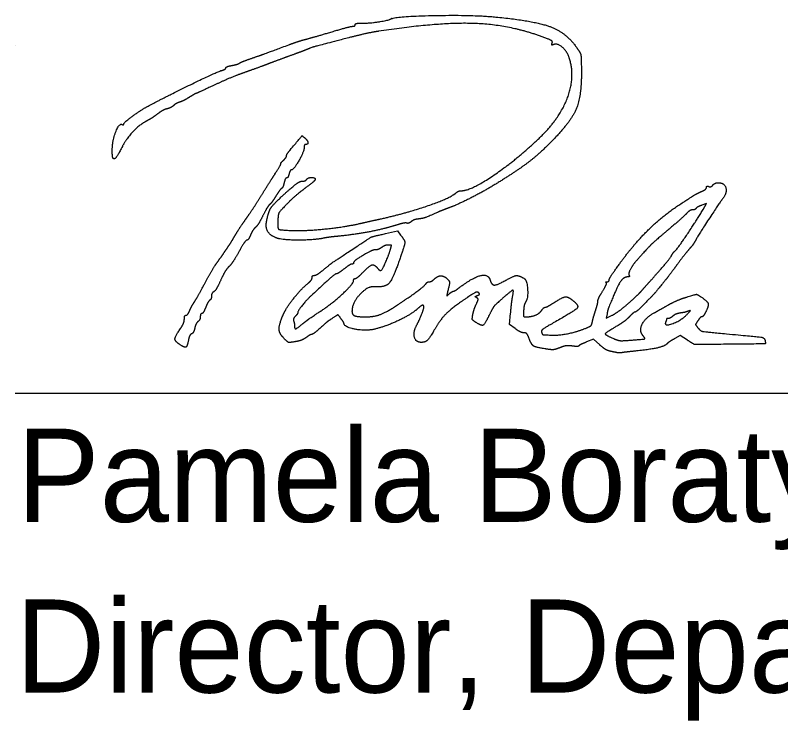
# Model space of a CAD drawing. Extents: x 0 to 34, y 0 to 22.
# Drawn here: x 25.87 to 27.021, y 4.243 to 5.303 of the extents above; entities that cross this region are included whole.
import ezdxf

# ---------------------------------------------------------------- set-up
doc = ezdxf.new("R2010")
doc.units = 0
for name, color, linetype in [('Default', 7, 'Continuous'), ('GM_X_Adjacent_County', 7, 'Continuous'), ('GM_X_Township', 7, 'Continuous')]:
    doc.layers.add(name, color=color, linetype=linetype)

msp = doc.modelspace()

# ---------------------------------------------------------------- linework, layer by layer
at = {"layer": 'Default'}
for points in [[(26.9038, 5.0114), (26.9092, 5.0203), (26.9019, 5.0178)], [(26.4265, 4.9752), (26.4445, 4.9793), (26.4492, 4.9731)], [(26.6215, 4.8324), (26.6131, 4.8388), (26.6146, 4.8558)], [(26.7595, 4.8544), (26.7584, 4.8479), (26.7671, 4.8524)], [(26.8803, 4.8151), (26.8696, 4.8219), (26.8613, 4.8174)], [(26.7484, 4.8081), (26.7393, 4.8164), (26.7287, 4.8123)]]:
    msp.add_lwpolyline(points, dxfattribs=at)
for points in [[(26.3899, 5.2916), (26.3995, 5.2913), (26.4305, 5.2957), (26.4339, 5.2978)], [(26.4339, 5.2978), (26.4407, 5.302), (26.5577, 5.3043), (26.5921, 5.3009)], [(26.5921, 5.3009), (26.6514, 5.2951), (26.6989, 5.2768), (26.7147, 5.2537)], [(26.3442, 5.2782), (26.3603, 5.283), (26.3751, 5.2869), (26.3772, 5.2869)], [(26.3772, 5.2869), (26.3792, 5.2869), (26.3809, 5.288), (26.3809, 5.2894)], [(26.3809, 5.2894), (26.3809, 5.2907), (26.385, 5.2917), (26.3899, 5.2916)], [(26.6646, 5.2702), (26.6141, 5.2892), (26.5061, 5.2931), (26.4157, 5.2794)], [(26.3053, 5.2671), (26.3106, 5.2684), (26.3281, 5.2734), (26.3442, 5.2782)], [(26.3713, 5.2697), (26.3203, 5.2565), (26.316, 5.2552), (26.3053, 5.2509)], [(26.4157, 5.2794), (26.4065, 5.278), (26.3865, 5.2736), (26.3713, 5.2697)], [(26.6769, 5.2615), (26.6779, 5.264), (26.6745, 5.2665), (26.6646, 5.2702)], [(26.2249, 5.2387), (26.2396, 5.2437), (26.2461, 5.2461), (26.2813, 5.2592)], [(26.2813, 5.2592), (26.2893, 5.2622), (26.3001, 5.2657), (26.3053, 5.2671)], [(26.6793, 5.2595), (26.6767, 5.2585), (26.676, 5.2591), (26.6769, 5.2615)], [(26.7027, 5.2395), (26.6995, 5.2493), (26.685, 5.2616), (26.6793, 5.2595)], [(26.3053, 5.2509), (26.3027, 5.2498), (26.2924, 5.246), (26.2825, 5.2424)], [(26.7147, 5.2537), (26.7197, 5.2465), (26.7206, 5.2421), (26.7209, 5.2243)], [(26.2069, 5.2315), (26.2083, 5.2325), (26.2164, 5.2357), (26.2249, 5.2387)], [(26.2825, 5.2424), (26.2726, 5.2388), (26.2575, 5.2332), (26.2489, 5.23)], [(26.6572, 5.1184), (26.6882, 5.1478), (26.712, 5.2113), (26.7027, 5.2395)], [(26.1811, 5.2208), (26.1841, 5.2217), (26.1865, 5.2233), (26.1865, 5.2244)], [(26.1865, 5.2244), (26.1865, 5.2254), (26.1906, 5.2271), (26.1955, 5.228)], [(26.1955, 5.228), (26.2005, 5.2289), (26.2056, 5.2305), (26.2069, 5.2315)], [(26.2489, 5.23), (26.2404, 5.2267), (26.2242, 5.2208), (26.2129, 5.2169)], [(26.7209, 5.2243), (26.7217, 5.1835), (26.7056, 5.1438), (26.6762, 5.1139)], [(26.0689, 5.1665), (26.0992, 5.1827), (26.1728, 5.2184), (26.1811, 5.2208)], [(26.2129, 5.2169), (26.2017, 5.2129), (26.1814, 5.2043), (26.1677, 5.1978)], [(26.1677, 5.1978), (26.1541, 5.1914), (26.1424, 5.1861), (26.1419, 5.1861)], [(26.1319, 5.1804), (26.127, 5.1773), (26.1203, 5.1739), (26.117, 5.1729)], [(26.1419, 5.1861), (26.1413, 5.1861), (26.1368, 5.1835), (26.1319, 5.1804)], [(26.0329, 5.1399), (26.0329, 5.142), (26.0583, 5.1608), (26.0689, 5.1665)], [(26.1079, 5.1678), (26.1061, 5.166), (26.1017, 5.1638), (26.0982, 5.1629)], [(26.117, 5.1729), (26.1138, 5.1719), (26.1097, 5.1696), (26.1079, 5.1678)], [(26.0833, 5.1548), (26.0787, 5.1513), (26.0716, 5.1466), (26.0674, 5.1445)], [(26.0982, 5.1629), (26.0946, 5.1621), (26.088, 5.1584), (26.0833, 5.1548)], [(26.0674, 5.1445), (26.057, 5.1392), (26.0371, 5.1183), (26.0309, 5.1062)], [(26.0158, 5.102), (26.0159, 5.1152), (26.0265, 5.1418), (26.0306, 5.1392)], [(26.0306, 5.1392), (26.0319, 5.1384), (26.0329, 5.1387), (26.0329, 5.1399)], [(26.2831, 5.1009), (26.3017, 5.1231), (26.301, 5.1225), (26.3051, 5.1191)], [(26.3065, 5.1093), (26.3052, 5.1093), (26.3041, 5.107), (26.3041, 5.1042)], [(26.3051, 5.1191), (26.3093, 5.1155), (26.3103, 5.1093), (26.3065, 5.1093)], [(26.5405, 5.0397), (26.5546, 5.0397), (26.6227, 5.0856), (26.6572, 5.1184)], [(26.6762, 5.1139), (26.6576, 5.095), (26.6252, 5.0701), (26.5947, 5.0513)], [(26.0171, 5.0883), (26.0163, 5.0891), (26.0157, 5.0952), (26.0158, 5.102)], [(26.0309, 5.1062), (26.0243, 5.0933), (26.019, 5.0864), (26.0171, 5.0883)], [(26.2777, 5.0923), (26.2777, 5.0935), (26.2802, 5.0974), (26.2831, 5.1009)], [(26.3041, 5.1042), (26.3041, 5.0986), (26.2882, 5.0709), (26.285, 5.0709)], [(26.2692, 5.0805), (26.2686, 5.0805), (26.2703, 5.0826), (26.2729, 5.0853)], [(26.2729, 5.0853), (26.2756, 5.0879), (26.2777, 5.0911), (26.2777, 5.0923)], [(26.2602, 5.0648), (26.2657, 5.0734), (26.2698, 5.0805), (26.2692, 5.0805)], [(26.2381, 5.0298), (26.2447, 5.0404), (26.2547, 5.0562), (26.2602, 5.0648)], [(26.2815, 5.0649), (26.2807, 5.0616), (26.2791, 5.0589), (26.2779, 5.0589)], [(26.285, 5.0709), (26.2839, 5.0709), (26.2824, 5.0682), (26.2815, 5.0649)], [(26.2693, 5.0299), (26.285, 5.0445), (26.2978, 5.0541), (26.3017, 5.0541)], [(26.2741, 5.0517), (26.2733, 5.0478), (26.2715, 5.0439), (26.2702, 5.0431)], [(26.2779, 5.0589), (26.2767, 5.0589), (26.275, 5.0556), (26.2741, 5.0517)], [(26.3017, 5.0541), (26.3042, 5.0541), (26.3069, 5.0552), (26.3077, 5.0565)], [(26.3209, 5.0568), (26.3209, 5.0557), (26.3142, 5.0498), (26.3059, 5.0437)], [(26.3077, 5.0565), (26.3095, 5.0594), (26.3209, 5.0597), (26.3209, 5.0568)], [(26.5947, 5.0513), (26.5755, 5.0394), (26.5342, 5.0184), (26.5201, 5.0133)], [(26.9186, 5.0482), (26.9202, 5.0501), (26.9239, 5.0517), (26.9268, 5.0517)], [(26.9268, 5.0517), (26.9363, 5.0517), (26.94, 5.0356), (26.9326, 5.0267)], [(26.2702, 5.0431), (26.269, 5.0423), (26.2652, 5.0372), (26.2618, 5.0317)], [(26.3059, 5.0437), (26.2977, 5.0376), (26.2852, 5.0268), (26.2781, 5.0196)], [(26.5323, 5.0363), (26.5344, 5.0382), (26.5381, 5.0397), (26.5405, 5.0397)], [(26.9011, 5.0383), (26.9054, 5.0402), (26.9089, 5.0431), (26.9089, 5.0446)], [(26.9089, 5.0446), (26.9089, 5.0461), (26.9105, 5.0468), (26.9124, 5.0461)], [(26.9124, 5.0461), (26.9142, 5.0453), (26.9171, 5.0463), (26.9186, 5.0482)], [(26.2164, 4.9969), (26.2217, 5.0043), (26.2315, 5.0192), (26.2381, 5.0298)], [(26.248, 4.9953), (26.2507, 5.0083), (26.2569, 5.0183), (26.2693, 5.0299)], [(26.2618, 5.0317), (26.2584, 5.0262), (26.2543, 5.0206), (26.2526, 5.0192)], [(26.4205, 4.9977), (26.4575, 5.0059), (26.5237, 5.0288), (26.5323, 5.0363)], [(26.8722, 5.0213), (26.8911, 5.0335), (26.8929, 5.0346), (26.9011, 5.0383)], [(26.2526, 5.0192), (26.2509, 5.0179), (26.2463, 5.0103), (26.2422, 5.0023)], [(26.2781, 5.0196), (26.2674, 5.0086), (26.2653, 5.005), (26.2647, 4.9967)], [(26.7775, 4.9288), (26.7998, 4.9596), (26.8448, 5.0036), (26.8722, 5.0213)], [(26.9326, 5.0267), (26.9285, 5.0216), (26.8956, 4.9712), (26.8925, 4.965)], [(26.9019, 5.0178), (26.8978, 5.0164), (26.8939, 5.0142), (26.8932, 5.013)], [(26.5045, 5.0071), (26.4874, 4.9997), (26.4825, 4.998), (26.4759, 4.9972)], [(26.5201, 5.0133), (26.5155, 5.0117), (26.5085, 5.0089), (26.5045, 5.0071)], [(26.879, 5.0055), (26.8763, 5.0025), (26.8639, 4.9914), (26.8513, 4.9809)], [(26.861, 4.9485), (26.8639, 4.9504), (26.8921, 4.9919), (26.9038, 5.0114)], [(26.8879, 5.0109), (26.8857, 5.0109), (26.8817, 5.0084), (26.879, 5.0055)], [(26.8932, 5.013), (26.8924, 5.0118), (26.8901, 5.0109), (26.8879, 5.0109)], [(26.1997, 4.9713), (26.2035, 4.9779), (26.211, 4.9894), (26.2164, 4.9969)], [(26.2422, 5.0023), (26.2382, 4.9943), (26.2332, 4.9863), (26.231, 4.9845)], [(26.2633, 4.9684), (26.2529, 4.9723), (26.2458, 4.9848), (26.248, 4.9953)], [(26.2647, 4.9967), (26.2639, 4.9833), (26.2679, 4.9804), (26.2885, 4.9799)], [(26.3869, 4.9902), (26.3949, 4.992), (26.41, 4.9954), (26.4205, 4.9977)], [(26.4759, 4.9972), (26.4721, 4.9968), (26.4672, 4.995), (26.4651, 4.9932)], [(26.231, 4.9845), (26.2288, 4.9827), (26.2256, 4.9777), (26.2237, 4.9733)], [(26.2885, 4.9799), (26.3078, 4.9793), (26.3656, 4.9854), (26.3869, 4.9902)], [(26.4403, 4.9873), (26.4239, 4.982), (26.3788, 4.9735), (26.355, 4.9712)], [(26.4583, 4.991), (26.4567, 4.9916), (26.4486, 4.9899), (26.4403, 4.9873)], [(26.4651, 4.9932), (26.463, 4.9914), (26.46, 4.9904), (26.4583, 4.991)], [(26.1866, 4.9506), (26.1899, 4.9554), (26.1958, 4.9647), (26.1997, 4.9713)], [(26.2237, 4.9733), (26.2219, 4.9689), (26.2193, 4.9653), (26.218, 4.9653)], [(26.355, 4.9712), (26.3466, 4.9704), (26.3375, 4.9692), (26.3346, 4.9686)], [(26.3725, 4.9488), (26.4042, 4.9698), (26.4056, 4.9705), (26.4265, 4.9752)], [(26.4492, 4.9731), (26.4558, 4.9643), (26.4557, 4.9595), (26.4479, 4.9369)], [(26.8513, 4.9809), (26.8317, 4.9644), (26.82, 4.953), (26.8033, 4.9341)], [(26.218, 4.9653), (26.2167, 4.9653), (26.2113, 4.9574), (26.206, 4.9477)], [(26.3346, 4.9686), (26.3209, 4.9655), (26.2714, 4.9654), (26.2633, 4.9684)], [(26.8925, 4.965), (26.8907, 4.9615), (26.8868, 4.9561), (26.8838, 4.9529)], [(26.1731, 4.9314), (26.1772, 4.9372), (26.1833, 4.9459), (26.1866, 4.9506)], [(26.206, 4.9477), (26.2006, 4.9381), (26.194, 4.9281), (26.1911, 4.9255)], [(26.3333, 4.9209), (26.347, 4.932), (26.3451, 4.9306), (26.3725, 4.9488)], [(26.4022, 4.9477), (26.3878, 4.9398), (26.3785, 4.9334), (26.3785, 4.9314)], [(26.4119, 4.9509), (26.4097, 4.9509), (26.4053, 4.9495), (26.4022, 4.9477)], [(26.4207, 4.9544), (26.4181, 4.9525), (26.4142, 4.9509), (26.4119, 4.9509)], [(26.4192, 4.9197), (26.421, 4.9197), (26.4307, 4.9408), (26.4339, 4.9515)], [(26.4306, 4.958), (26.4277, 4.958), (26.4232, 4.9563), (26.4207, 4.9544)], [(26.4339, 4.9515), (26.4356, 4.9573), (26.4351, 4.9581), (26.4306, 4.958)], [(26.8571, 4.9433), (26.8583, 4.9455), (26.8601, 4.9478), (26.861, 4.9485)], [(26.8838, 4.9529), (26.8809, 4.9496), (26.8719, 4.9383), (26.8641, 4.9276)], [(26.4479, 4.9369), (26.4377, 4.907), (26.4257, 4.894), (26.4097, 4.8953)], [(26.8258, 4.9055), (26.8412, 4.9226), (26.8547, 4.939), (26.8571, 4.9433)], [(26.1542, 4.8993), (26.1605, 4.9112), (26.169, 4.9256), (26.1731, 4.9314)], [(26.1911, 4.9255), (26.1883, 4.923), (26.1827, 4.9139), (26.1788, 4.9053)], [(26.3759, 4.9293), (26.3744, 4.9293), (26.3691, 4.926), (26.3641, 4.9221)], [(26.3785, 4.9314), (26.3785, 4.9302), (26.3773, 4.9293), (26.3759, 4.9293)], [(26.3929, 4.9173), (26.4031, 4.9274), (26.4096, 4.9292), (26.4145, 4.9233)], [(26.7625, 4.9054), (26.7625, 4.9069), (26.7693, 4.9174), (26.7775, 4.9288)], [(26.8033, 4.9341), (26.7975, 4.9275), (26.7912, 4.9146), (26.7927, 4.9123)], [(26.8641, 4.9276), (26.8562, 4.917), (26.8485, 4.9068), (26.847, 4.905)], [(26.353, 4.9149), (26.3511, 4.9148), (26.3426, 4.9076), (26.3173, 4.8843)], [(26.3195, 4.9125), (26.3214, 4.9125), (26.3276, 4.9163), (26.3333, 4.9209)], [(26.3641, 4.9221), (26.3591, 4.9181), (26.3541, 4.9149), (26.353, 4.9149)], [(26.3809, 4.9077), (26.3823, 4.9077), (26.3877, 4.912), (26.3929, 4.9173)], [(26.4145, 4.9233), (26.4162, 4.9213), (26.4183, 4.9197), (26.4192, 4.9197)], [(26.5377, 4.8942), (26.5579, 4.9094), (26.5807, 4.915), (26.5836, 4.9055)], [(26.1788, 4.9053), (26.1749, 4.8967), (26.1702, 4.8888), (26.1683, 4.8878)], [(26.2726, 4.853), (26.2771, 4.8635), (26.3004, 4.8929), (26.3107, 4.9012)], [(26.3107, 4.9012), (26.3137, 4.9037), (26.3161, 4.9072), (26.3161, 4.909)], [(26.3161, 4.909), (26.3161, 4.9109), (26.3176, 4.9125), (26.3195, 4.9125)], [(26.3325, 4.8611), (26.348, 4.8715), (26.3785, 4.9002), (26.3785, 4.9045)], [(26.3785, 4.9045), (26.3785, 4.9063), (26.3796, 4.9077), (26.3809, 4.9077)], [(26.4873, 4.8998), (26.4883, 4.9015), (26.4907, 4.9029), (26.4925, 4.9029)], [(26.4925, 4.9029), (26.4943, 4.9029), (26.4975, 4.9046), (26.4997, 4.9068)], [(26.4997, 4.9068), (26.5047, 4.9117), (26.5146, 4.9118), (26.5196, 4.9069)], [(26.5196, 4.9069), (26.5227, 4.9037), (26.523, 4.9012), (26.5209, 4.8921)], [(26.5836, 4.9055), (26.5861, 4.8979), (26.5941, 4.8978), (26.6074, 4.9052)], [(26.6074, 4.9052), (26.6194, 4.9118), (26.6266, 4.9125), (26.6348, 4.9079)], [(26.6348, 4.9079), (26.6392, 4.9055), (26.6409, 4.8774), (26.637, 4.8723)], [(26.7528, 4.8886), (26.7566, 4.8949), (26.7592, 4.9006), (26.7584, 4.9014)], [(26.7584, 4.9014), (26.7576, 4.9022), (26.7582, 4.9029), (26.7597, 4.9029)], [(26.7597, 4.9029), (26.7613, 4.9029), (26.7625, 4.904), (26.7625, 4.9054)], [(26.7904, 4.9101), (26.7841, 4.9101), (26.7745, 4.8949), (26.7625, 4.8657)], [(26.7927, 4.9123), (26.7934, 4.9111), (26.7924, 4.9101), (26.7904, 4.9101)], [(26.8102, 4.888), (26.8134, 4.8916), (26.8204, 4.8994), (26.8258, 4.9055)], [(26.847, 4.905), (26.8337, 4.8886), (26.8292, 4.8834), (26.8173, 4.8712)], [(26.1387, 4.8717), (26.1409, 4.875), (26.1479, 4.8874), (26.1542, 4.8993)], [(26.4097, 4.8953), (26.3993, 4.8962), (26.3761, 4.8708), (26.3761, 4.8586)], [(26.4445, 4.868), (26.4631, 4.8804), (26.4855, 4.897), (26.4873, 4.8998)], [(26.5209, 4.8921), (26.5185, 4.8818), (26.5186, 4.8813), (26.5224, 4.8848)], [(26.5283, 4.8885), (26.5293, 4.8885), (26.5335, 4.891), (26.5377, 4.8942)], [(26.6176, 4.8807), (26.6194, 4.8901), (26.6168, 4.8905), (26.6075, 4.8823)], [(26.1649, 4.8813), (26.1649, 4.8788), (26.1638, 4.8761), (26.1624, 4.8752)], [(26.1683, 4.8878), (26.1664, 4.8867), (26.1649, 4.8838), (26.1649, 4.8813)], [(26.3173, 4.8843), (26.3082, 4.876), (26.2945, 4.8589), (26.2945, 4.8559)], [(26.5224, 4.8848), (26.5247, 4.8868), (26.5273, 4.8885), (26.5283, 4.8885)], [(26.5664, 4.8864), (26.5646, 4.8882), (26.5587, 4.8854), (26.5462, 4.8769)], [(26.5635, 4.8788), (26.5613, 4.8801), (26.5616, 4.881), (26.5647, 4.8822)], [(26.5628, 4.8689), (26.5657, 4.8752), (26.5658, 4.8773), (26.5635, 4.8788)], [(26.5647, 4.8822), (26.5677, 4.8834), (26.5682, 4.8846), (26.5664, 4.8864)], [(26.6075, 4.8823), (26.5916, 4.8683), (26.5878, 4.8639), (26.5823, 4.8525)], [(26.6146, 4.8558), (26.6154, 4.8652), (26.6167, 4.8764), (26.6176, 4.8807)], [(26.6801, 4.8717), (26.6931, 4.8799), (26.7007, 4.8807), (26.7083, 4.8746)], [(26.7457, 4.8738), (26.7457, 4.8756), (26.7489, 4.8823), (26.7528, 4.8886)], [(26.7901, 4.8692), (26.7981, 4.876), (26.8071, 4.8845), (26.8102, 4.888)], [(26.8501, 4.8672), (26.8581, 4.8717), (26.8712, 4.8774), (26.8794, 4.8799)], [(26.8794, 4.8799), (26.8935, 4.8841), (26.8947, 4.8841), (26.9005, 4.8803)], [(26.9005, 4.8803), (26.9101, 4.874), (26.9126, 4.8666), (26.9079, 4.8576)], [(26.1319, 4.8591), (26.1334, 4.8627), (26.1365, 4.8684), (26.1387, 4.8717)], [(26.1624, 4.8752), (26.1611, 4.8744), (26.1582, 4.8694), (26.1562, 4.8643)], [(26.3961, 4.8501), (26.4091, 4.8501), (26.4282, 4.8571), (26.4445, 4.868)], [(26.4841, 4.8648), (26.4841, 4.8678), (26.4802, 4.8673), (26.4765, 4.8638)], [(26.5462, 4.8769), (26.5264, 4.8635), (26.5092, 4.8465), (26.5009, 4.8321)], [(26.5577, 4.8533), (26.5585, 4.8575), (26.5608, 4.8645), (26.5628, 4.8689)], [(26.637, 4.8723), (26.6358, 4.8706), (26.6344, 4.8649), (26.6341, 4.8597)], [(26.6666, 4.8645), (26.6678, 4.8645), (26.6739, 4.8677), (26.6801, 4.8717)], [(26.7083, 4.8746), (26.718, 4.867), (26.7112, 4.8591), (26.6796, 4.8414)], [(26.7422, 4.8597), (26.7442, 4.8656), (26.7457, 4.872), (26.7457, 4.8738)], [(26.7671, 4.8524), (26.7718, 4.8548), (26.7822, 4.8624), (26.7901, 4.8692)], [(26.8173, 4.8712), (26.8098, 4.8635), (26.8028, 4.8573), (26.8017, 4.8573)], [(26.8306, 4.8562), (26.8334, 4.8577), (26.8422, 4.8627), (26.8501, 4.8672)], [(26.1266, 4.8525), (26.1279, 4.8525), (26.1303, 4.8554), (26.1319, 4.8591)], [(26.1562, 4.8643), (26.1541, 4.8591), (26.1514, 4.8549), (26.1503, 4.8549)], [(26.2945, 4.8559), (26.2945, 4.8552), (26.2928, 4.8528), (26.2908, 4.8508)], [(26.3009, 4.8388), (26.3085, 4.8449), (26.3137, 4.8486), (26.3325, 4.8611)], [(26.3761, 4.8586), (26.3761, 4.8534), (26.3839, 4.8501), (26.3961, 4.8501)], [(26.4765, 4.8638), (26.4669, 4.8547), (26.4282, 4.8359), (26.4097, 4.8315)], [(26.4736, 4.8381), (26.4777, 4.8457), (26.4841, 4.862), (26.4841, 4.8648)], [(26.6341, 4.8597), (26.6336, 4.8521), (26.6343, 4.8501), (26.6374, 4.8501)], [(26.6374, 4.8501), (26.6457, 4.8501), (26.6577, 4.8549), (26.661, 4.8596)], [(26.661, 4.8596), (26.6629, 4.8623), (26.6654, 4.8645), (26.6666, 4.8645)], [(26.7375, 4.8426), (26.7381, 4.8461), (26.7403, 4.8537), (26.7422, 4.8597)], [(26.7625, 4.8657), (26.7614, 4.863), (26.76, 4.858), (26.7595, 4.8544)], [(26.8017, 4.8573), (26.8006, 4.8573), (26.7968, 4.8541), (26.7931, 4.8503)], [(26.8135, 4.8218), (26.8074, 4.8292), (26.8172, 4.849), (26.8306, 4.8562)], [(26.8695, 4.8558), (26.8657, 4.8553), (26.8607, 4.8532), (26.8585, 4.8513)], [(26.8813, 4.8585), (26.8787, 4.8575), (26.8734, 4.8563), (26.8695, 4.8558)], [(26.8789, 4.853), (26.8844, 4.8586), (26.885, 4.8599), (26.8813, 4.8585)], [(26.9079, 4.8576), (26.9058, 4.8535), (26.9031, 4.8501), (26.9019, 4.8501)], [(26.1183, 4.8326), (26.1215, 4.8373), (26.1241, 4.8437), (26.1241, 4.8468)], [(26.1241, 4.8468), (26.1241, 4.8499), (26.1252, 4.8525), (26.1266, 4.8525)], [(26.1481, 4.8504), (26.1481, 4.8479), (26.1466, 4.8446), (26.1447, 4.843)], [(26.1503, 4.8549), (26.1491, 4.8549), (26.1481, 4.8528), (26.1481, 4.8504)], [(26.2743, 4.8173), (26.2667, 4.8249), (26.2661, 4.8377), (26.2726, 4.853)], [(26.2908, 4.8508), (26.2887, 4.8487), (26.2877, 4.8455), (26.2884, 4.8436)], [(26.3482, 4.8489), (26.34, 4.8435), (26.3375, 4.8415), (26.3263, 4.8315)], [(26.3595, 4.8475), (26.3551, 4.8533), (26.355, 4.8533), (26.3482, 4.8489)], [(26.3641, 4.8401), (26.364, 4.841), (26.362, 4.8443), (26.3595, 4.8475)], [(26.5623, 4.8418), (26.5574, 4.845), (26.5566, 4.847), (26.5577, 4.8533)], [(26.5823, 4.8525), (26.5757, 4.8388), (26.5708, 4.8362), (26.5623, 4.8418)], [(26.7931, 4.8503), (26.7895, 4.8465), (26.7814, 4.8404), (26.7752, 4.8367)], [(26.8475, 4.8419), (26.845, 4.8354), (26.8705, 4.8444), (26.8789, 4.853)], [(26.8489, 4.8467), (26.8489, 4.8461), (26.8483, 4.844), (26.8475, 4.8419)], [(26.8517, 4.8477), (26.8502, 4.8477), (26.8489, 4.8472), (26.8489, 4.8467)], [(26.8585, 4.8513), (26.8563, 4.8493), (26.8533, 4.8477), (26.8517, 4.8477)], [(26.8961, 4.8443), (26.8926, 4.8389), (26.8926, 4.838), (26.8964, 4.8333)], [(26.9019, 4.8501), (26.9008, 4.8501), (26.8982, 4.8475), (26.8961, 4.8443)], [(26.1166, 4.8089), (26.1096, 4.8137), (26.1101, 4.8205), (26.1183, 4.8326)], [(26.1397, 4.8329), (26.1388, 4.829), (26.1367, 4.8252), (26.1349, 4.8245)], [(26.1447, 4.843), (26.1428, 4.8414), (26.1405, 4.8369), (26.1397, 4.8329)], [(26.2884, 4.8436), (26.2891, 4.8416), (26.2897, 4.8385), (26.2897, 4.8367)], [(26.2897, 4.8367), (26.2897, 4.8318), (26.2932, 4.8325), (26.3009, 4.8388)], [(26.4097, 4.8315), (26.3969, 4.8284), (26.3643, 4.8346), (26.3641, 4.8401)], [(26.4803, 4.8117), (26.4719, 4.8117), (26.4679, 4.8275), (26.4736, 4.8381)], [(26.6345, 4.8261), (26.6319, 4.8261), (26.626, 4.8289), (26.6215, 4.8324)], [(26.6796, 4.8414), (26.6664, 4.834), (26.6601, 4.8291), (26.661, 4.827)], [(26.7248, 4.832), (26.7336, 4.8353), (26.7365, 4.8378), (26.7375, 4.8426)], [(26.7752, 4.8367), (26.7572, 4.8263), (26.7562, 4.823), (26.7691, 4.8175)], [(26.8964, 4.8333), (26.9001, 4.8288), (26.905, 4.8278), (26.9389, 4.8246)], [(26.1349, 4.8245), (26.1332, 4.8239), (26.1311, 4.8197), (26.1303, 4.8153)], [(26.3155, 4.8237), (26.3144, 4.8237), (26.3106, 4.8215), (26.307, 4.8189)], [(26.3263, 4.8315), (26.3215, 4.8272), (26.3166, 4.8237), (26.3155, 4.8237)], [(26.5009, 4.8321), (26.4927, 4.818), (26.4864, 4.8117), (26.4803, 4.8117)], [(26.642, 4.8183), (26.6401, 4.8234), (26.6376, 4.8261), (26.6345, 4.8261)], [(26.661, 4.827), (26.6623, 4.8235), (26.663, 4.8233), (26.6749, 4.8226)], [(26.6749, 4.8226), (26.6855, 4.822), (26.7116, 4.8269), (26.7248, 4.832)], [(26.7959, 4.8151), (26.8155, 4.8166), (26.8172, 4.8173), (26.8135, 4.8218)], [(26.9389, 4.8246), (26.988, 4.8201), (26.9963, 4.8186), (26.9972, 4.8138)], [(26.1303, 4.8153), (26.1285, 4.8056), (26.1243, 4.8036), (26.1166, 4.8089)], [(26.2905, 4.8127), (26.2818, 4.8113), (26.2797, 4.8119), (26.2743, 4.8173)], [(26.307, 4.8189), (26.3035, 4.8163), (26.296, 4.8135), (26.2905, 4.8127)], [(26.6674, 4.8018), (26.6523, 4.8042), (26.6455, 4.8086), (26.642, 4.8183)], [(26.7287, 4.8123), (26.7229, 4.81), (26.7178, 4.8075), (26.7174, 4.8066)], [(26.7691, 4.8175), (26.776, 4.8146), (26.7824, 4.814), (26.7959, 4.8151)], [(26.8496, 4.8095), (26.8458, 4.8058), (26.8243, 4.8009), (26.8009, 4.7985)], [(26.8613, 4.8174), (26.8567, 4.8149), (26.8514, 4.8114), (26.8496, 4.8095)], [(26.9269, 4.8087), (26.8912, 4.8083), (26.8908, 4.8083), (26.8803, 4.8151)], [(26.9972, 4.8138), (26.998, 4.8095), (26.9961, 4.8094), (26.9269, 4.8087)], [(26.6885, 4.8037), (26.6815, 4.8009), (26.6759, 4.8004), (26.6674, 4.8018)], [(26.7073, 4.8062), (26.7016, 4.807), (26.6943, 4.806), (26.6885, 4.8037)], [(26.7174, 4.8066), (26.717, 4.8057), (26.7125, 4.8055), (26.7073, 4.8062)], [(26.7631, 4.7986), (26.7601, 4.7993), (26.7535, 4.8035), (26.7484, 4.8081)], [(26.7733, 4.7965), (26.7707, 4.797), (26.7661, 4.798), (26.7631, 4.7986)], [(26.8009, 4.7985), (26.7924, 4.7976), (26.7837, 4.7966), (26.7817, 4.7962)], [(26.7817, 4.7962), (26.7798, 4.7958), (26.776, 4.7959), (26.7733, 4.7965)]]:
    msp.add_open_spline(points, degree=2, dxfattribs=at)
at = {"layer": 'GM_X_Township'}
for p, q in [((25.87, 5.2574), (25.87, 5.2574)), ((25.87, 4.7352), (29.37, 4.7352))]:
    msp.add_line(p, q, dxfattribs=at)

# ---------------------------------------------------------------- texts
at = {"layer": 'GM_X_Adjacent_County'}
for s, p in [('Pamela Boratyn', (25.872, 4.5419)), ('Director, Department of Transportation', (25.87, 4.2852))]:
    msp.add_text(s, height=0.14, dxfattribs=at).set_placement(p)

doc.saveas('drawing.dxf')
